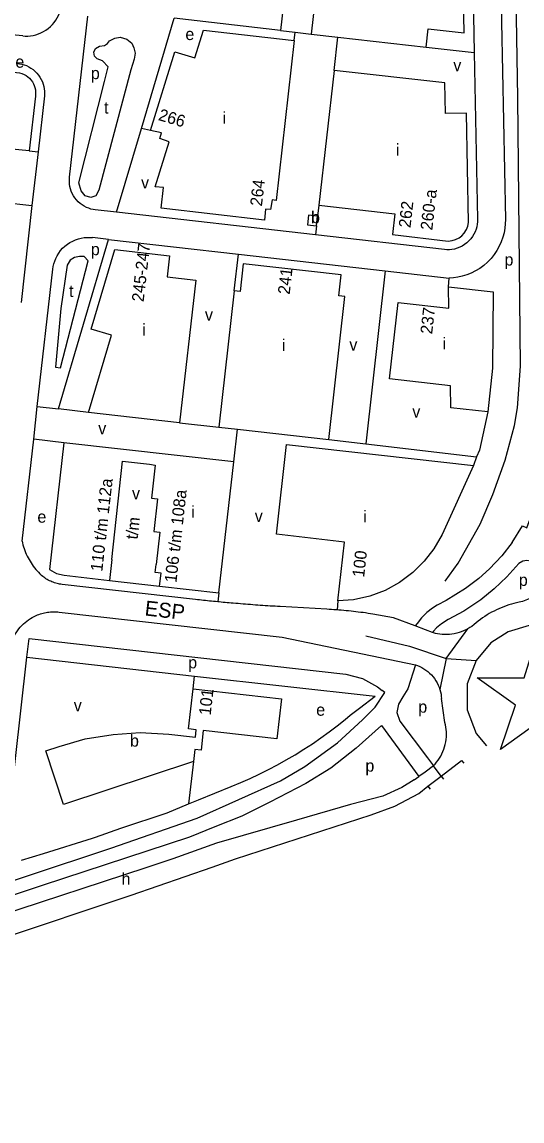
# Model space of a CAD drawing. Extents: x 161394 to 163917, y 388470 to 389774.
# Drawn here: x 162341 to 162508, y 388499 to 388866.6 of the extents above; entities that cross this region are included whole.
import ezdxf

# ---------------------------------------------------------------- set-up
doc = ezdxf.new("R2010")
doc.units = 0
for name, color, linetype in [('BLT_Basislijn', 7, 'Continuous'), ('BLT_Bebouwing', 7, 'Continuous'), ('BLT_Centroide', 7, 'Continuous'), ('BLT_Huisnummer', 7, 'Continuous'), ('BLT_Huisnummer_reeks', 7, 'Continuous'), ('BLT_Straatnaam', 7, 'Continuous'), ('BLT_Vlakafsluiter', 7, 'Continuous')]:
    doc.layers.add(name, color=color, linetype=linetype)

msp = doc.modelspace()

# ---------------------------------------------------------------- linework, layer by layer
at = {"layer": 'BLT_Basislijn'}
for p, q in [((162506.63, 388841.21), (162505.13, 388944.2)), ((162491.22, 388898.12), (162492.06, 388856.45)), ((162356.83, 388814.71), (162362.93, 388868.63)), ((162427.37, 388863.83), (162432.26, 388863.19)), ((162431.95, 388860.46), (162432.26, 388863.19)), ((162432.26, 388863.19), (162437.61, 388862.58)), ((162365.5, 388857.74), (162366.81, 388858.52)), ((162366.81, 388858.52), (162368.51, 388858.75)), ((162368.51, 388858.75), (162369.48, 388859.46)), ((162369.48, 388859.46), (162370.25, 388860.33)), ((162370.25, 388860.33), (162372.01, 388861.18)), ((162372.01, 388861.18), (162373.71, 388861.54)), ((162373.71, 388861.54), (162376.04, 388860.94)), ((162376.04, 388860.94), (162377.68, 388859.56)), ((162377.68, 388859.56), (162378.32, 388858.02)), ((162445.29, 388850.44), (162446.55, 388861.57)), ((162476.03, 388858.25), (162492.06, 388856.45)), ((162365.01, 388856.53), (162365.5, 388857.74)), ((162365.22, 388855.15), (162365.01, 388856.53)), ((162366.1, 388854.3), (162365.22, 388855.15)), ((162378.32, 388858.02), (162378.75, 388856.22)), ((162378.75, 388856.22), (162378.42, 388854.16)), ((162492.06, 388856.45), (162493.18, 388800.64)), ((162367.88, 388853.65), (162366.1, 388854.3)), ((162369.8, 388851.68), (162367.88, 388853.65)), ((162368.53, 388846.69), (162369.8, 388851.68)), ((162378.42, 388854.16), (162377.35, 388850.68)), ((162377.35, 388850.68), (162366.67, 388810.36)), ((162359.93, 388812.83), (162368.53, 388846.69)), ((162348.44, 388841.91), (162346.32, 388823.16)), ((162383.92, 388830.34), (162380.86, 388831)), ((162343.36, 388823.49), (162346.32, 388823.16)), ((162346.32, 388823.16), (162344.29, 388805.2)), ((162360.73, 388810.11), (162359.93, 388812.83)), ((162366.67, 388810.36), (162365.66, 388808.47)), ((162362.09, 388808.52), (162360.73, 388810.11)), ((162363.93, 388807.98), (162362.09, 388808.52)), ((162365.66, 388808.47), (162363.93, 388807.98)), ((162334.33, 388806.33), (162344.29, 388805.2)), ((162344.29, 388805.2), (162340.62, 388772.81)), ((162372.51, 388802.97), (162365.46, 388803.77)), ((162440.17, 388805.32), (162439.74, 388801.68)), ((162439.04, 388795.4), (162372.51, 388802.97)), ((162439.37, 388798.4), (162439.04, 388795.4)), ((162369.83, 388793.91), (162364.52, 388794.52)), ((162482.16, 388790.5), (162439.04, 388795.4)), ((162411.87, 388776.7), (162413.31, 388788.98)), ((162353.86, 388750.98), (162363.07, 388786.74)), ((162356.06, 388785.34), (162353.92, 388770.75)), ((162357.04, 388786.95), (162356.06, 388785.34)), ((162358.52, 388787.88), (162357.04, 388786.95)), ((162360.21, 388788.15), (162358.52, 388787.88)), ((162361.75, 388788.14), (162360.21, 388788.15)), ((162363.07, 388786.74), (162361.75, 388788.14)), ((162462.34, 388783.42), (162455.81, 388725.56)), ((162483.49, 388778.03), (162483.67, 388781)), ((162353.92, 388770.75), (162352.19, 388751.13)), ((162352.19, 388751.13), (162353.86, 388750.98)), ((162346.05, 388738.07), (162353.11, 388737.24)), ((162363.2, 388736.02), (162353.11, 388737.24)), ((162393.63, 388732.56), (162406.69, 388731.15)), ((162411.71, 388719.46), (162412.95, 388730.43)), ((162354.96, 388725.92), (162344.88, 388727.07)), ((162443.44, 388726.97), (162455.81, 388725.56)), ((162455.81, 388725.56), (162492.89, 388721.19)), ((162492.89, 388721.19), (162491.88, 388718.3)), ((162398.97, 388673.46), (162354.42, 388678.5)), ((162406.74, 388675.66), (162406.4, 388672.68)), ((162442.77, 388670.22), (162427.2, 388671.08)), ((162446.49, 388673), (162446.28, 388669.98)), ((162472.34, 388664.6), (162465.1, 388667.35)), ((162475.81, 388663.28), (162472.34, 388664.6)), ((162478.12, 388662.41), (162475.81, 388663.28)), ((162336.75, 388602.35), (162342.6, 388654.12)), ((162472.44, 388651.57), (162469.91, 388643.61)), ((162398.15, 388643.62), (162398.63, 388647.87)), ((162458.99, 388637.41), (162462.26, 388642.32)), ((162462.26, 388642.32), (162461.36, 388643.04)), ((162482.28, 388632.36), (162481.13, 388640.3)), ((162461.09, 388631.3), (162473.61, 388614.26)), ((162398.29, 388619.33), (162396.64, 388605.08)), ((162476.44, 388620.48), (162478.46, 388617.83)), ((162475.64, 388615.75), (162473.61, 388614.26)), ((162478.46, 388617.83), (162475.64, 388615.75)), ((162472.04, 388613.1), (162473.61, 388614.26)), ((162481.05, 388614.41), (162481.82, 388613.39)), ((162476.62, 388610.98), (162477.39, 388609.97)), ((162382.33, 388583.76), (162305.41, 388558.5)), ((162214.71, 388520.22), (162377.39, 388574.62))]:
    msp.add_line(p, q, dxfattribs=at)
for points in [[(162495.1, 389075.02), (162497.51, 389048.21), (162502.48, 388800.58)], [(162341.2, 388861.95), (162241.66, 388870.97)], [(162341.2, 388861.95), (162342.04, 388861.9), (162342.9, 388861.91), (162343.78, 388861.99), (162344.67, 388862.13), (162345.55, 388862.35), (162346.43, 388862.64), (162347.3, 388862.99), (162348.13, 388863.42), (162348.94, 388863.91), (162349.71, 388864.47), (162350.43, 388865.08), (162351.1, 388865.75), (162351.7, 388866.46), (162352.25, 388867.21), (162352.73, 388867.98), (162353.14, 388868.78), (162353.49, 388869.59), (162353.77, 388870.4), (162353.94, 388871.01)], [(162380.86, 388831), (162391.86, 388867.87)], [(162339.39, 388852.77), (162340.14, 388852.68), (162340.9, 388852.53), (162341.67, 388852.31), (162342.44, 388852.03), (162343.19, 388851.67), (162343.92, 388851.24), (162344.63, 388850.75), (162345.29, 388850.19), (162345.91, 388849.57), (162346.47, 388848.9), (162346.96, 388848.18), (162347.39, 388847.43), (162347.75, 388846.65), (162348.04, 388845.85), (162348.25, 388845.04), (162348.4, 388844.24), (162348.47, 388843.44), (162348.49, 388842.67), (162348.44, 388841.91)], [(162502.45, 388720.06), (162505.5, 388731.68), (162506.52, 388737.54), (162507.51, 388751.47), (162506.63, 388841.21)], [(162372.51, 388802.97), (162380.86, 388831)], [(162365.46, 388803.77), (162364.73, 388803.89), (162363.98, 388804.07), (162363.24, 388804.31), (162362.5, 388804.62), (162361.77, 388804.99), (162361.06, 388805.44), (162360.39, 388805.94), (162359.76, 388806.51), (162359.17, 388807.13), (162358.64, 388807.81), (162358.17, 388808.52), (162357.77, 388809.27), (162357.43, 388810.04), (162357.16, 388810.83), (162356.97, 388811.63), (162356.84, 388812.42), (162356.78, 388813.2), (162356.78, 388813.97), (162356.83, 388814.71)], [(162493.18, 388800.64), (162493.17, 388799.83), (162493.09, 388799.01), (162492.94, 388798.17), (162492.71, 388797.32), (162492.4, 388796.48), (162492, 388795.65), (162491.52, 388794.85), (162490.96, 388794.09), (162490.33, 388793.38), (162489.63, 388792.74), (162488.87, 388792.17), (162488.07, 388791.67), (162487.23, 388791.26), (162486.37, 388790.93), (162485.51, 388790.69), (162484.64, 388790.53), (162483.79, 388790.45), (162482.96, 388790.44), (162482.16, 388790.5)], [(162502.48, 388800.58), (162502.45, 388799.13), (162502.31, 388797.64), (162502.05, 388796.14), (162501.65, 388794.62), (162501.13, 388793.11), (162500.46, 388791.63), (162499.67, 388790.19), (162498.74, 388788.81), (162497.7, 388787.51), (162496.54, 388786.3), (162495.28, 388785.2), (162493.94, 388784.22), (162492.53, 388783.37), (162491.08, 388782.65), (162489.59, 388782.06), (162488.09, 388781.61), (162486.6, 388781.28), (162485.12, 388781.08), (162483.67, 388781)], [(162351.24, 388783.94), (162351.38, 388784.84), (162351.59, 388785.75), (162351.88, 388786.66), (162352.24, 388787.57), (162352.7, 388788.46), (162353.23, 388789.32), (162353.84, 388790.15), (162354.53, 388790.93), (162355.29, 388791.65), (162356.11, 388792.3), (162356.98, 388792.88), (162357.89, 388793.37), (162358.83, 388793.78), (162359.79, 388794.11), (162360.76, 388794.35), (162361.73, 388794.51), (162362.68, 388794.58), (162363.62, 388794.59), (162364.52, 388794.52)], [(162353.11, 388737.24), (162369.83, 388793.91)], [(162369.83, 388793.91), (162413.31, 388788.98)], [(162413.31, 388788.98), (162462.34, 388783.42)], [(162346.05, 388738.07), (162351.24, 388783.94)], [(162462.34, 388783.42), (162483.67, 388781)], [(162504.76, 388692.48), (162508.27, 388698.15), (162509.67, 388697.38), (162515.69, 388713.62), (162516.59, 388719.1), (162516.71, 388731.13), (162517.37, 388777.82)], [(162344.88, 388727.07), (162346.05, 388738.07)], [(162496.59, 388736.18), (162493.83, 388723.46), (162492.89, 388721.19)], [(162340.96, 388693.01), (162344.88, 388727.07)], [(162482.39, 388679.55), (162486.74, 388685.56), (162494.04, 388698.67), (162498.29, 388708.58), (162502.45, 388720.06)], [(162340.96, 388693.01), (162341.11, 388692.37), (162341.28, 388691.73), (162341.46, 388691.1), (162341.67, 388690.47), (162341.9, 388689.85), (162342.14, 388689.23), (162342.4, 388688.62), (162342.68, 388688.01), (162342.99, 388687.42), (162343.3, 388686.83), (162343.64, 388686.25), (162343.99, 388685.69), (162344.36, 388685.13), (162344.74, 388684.59), (162345.14, 388684.06), (162345.55, 388683.54), (162345.98, 388683.04), (162346.42, 388682.55), (162346.87, 388682.07)], [(162504.76, 388692.48), (162501.27, 388688.08), (162497.22, 388683.77), (162493.59, 388680.46), (162489.12, 388677.13), (162482.69, 388673.13), (162479.71, 388671.62), (162478.09, 388670.6), (162476.19, 388669.06), (162474.48, 388667.31), (162472.96, 388665.39), (162472.34, 388664.6)], [(162510.87, 388686.25), (162509.61, 388686.46), (162508.35, 388686.31), (162507.01, 388685.54), (162503.02, 388681.07), (162498.79, 388677.01), (162494.25, 388673.31), (162488.61, 388669.52), (162483.41, 388666.77), (162481.14, 388665.29), (162479.49, 388663.98), (162478.46, 388662.9), (162478.12, 388662.41)], [(162354.42, 388678.5), (162353.98, 388678.56), (162353.54, 388678.63), (162353.11, 388678.72), (162352.67, 388678.82), (162352.24, 388678.94), (162351.81, 388679.07), (162351.38, 388679.22), (162350.96, 388679.39), (162350.55, 388679.57), (162350.14, 388679.76), (162349.74, 388679.97), (162349.35, 388680.19), (162348.96, 388680.42), (162348.59, 388680.67), (162348.22, 388680.93), (162347.87, 388681.2), (162347.52, 388681.48), (162347.19, 388681.77), (162346.87, 388682.07)], [(162370.18, 388679.81), (162386.95, 388677.95)], [(162515.67, 388679.32), (162515.41, 388678.8), (162515.13, 388678.28), (162514.83, 388677.78), (162514.49, 388677.29), (162514.13, 388676.81), (162513.74, 388676.35), (162513.33, 388675.9), (162512.89, 388675.48), (162512.43, 388675.08), (162511.96, 388674.7), (162511.46, 388674.34), (162510.95, 388674.02), (162510.42, 388673.71), (162509.88, 388673.44), (162509.33, 388673.2), (162508.78, 388672.99), (162508.21, 388672.8), (162507.65, 388672.64), (162507.09, 388672.52)], [(162406.4, 388672.68), (162405.58, 388672.76), (162404.92, 388672.83), (162404.26, 388672.89), (162403.6, 388672.96), (162402.93, 388673.03), (162402.27, 388673.1), (162401.61, 388673.17), (162400.95, 388673.24), (162400.29, 388673.32), (162399.63, 388673.39), (162398.97, 388673.46)], [(162411.53, 388672.22), (162410.87, 388672.28), (162410.21, 388672.33), (162409.55, 388672.39), (162408.89, 388672.45), (162408.22, 388672.51), (162407.56, 388672.57), (162406.9, 388672.64), (162406.4, 388672.68)], [(162427.2, 388671.08), (162426.37, 388671.13), (162425.55, 388671.18), (162424.72, 388671.23), (162423.9, 388671.28), (162423.07, 388671.33), (162422.25, 388671.38), (162421.42, 388671.44), (162420.6, 388671.49), (162419.77, 388671.55), (162418.95, 388671.61), (162418.12, 388671.67), (162417.3, 388671.74), (162416.48, 388671.8), (162415.65, 388671.87), (162414.83, 388671.93), (162414, 388672), (162413.18, 388672.08), (162412.36, 388672.15), (162411.53, 388672.22)], [(162507.09, 388672.52), (162506.22, 388672.33), (162505.36, 388672.12), (162504.51, 388671.89), (162503.66, 388671.64), (162502.81, 388671.36), (162501.97, 388671.05), (162501.14, 388670.73), (162500.32, 388670.37), (162499.5, 388670), (162498.7, 388669.6), (162497.91, 388669.18), (162497.13, 388668.75), (162496.37, 388668.29), (162495.61, 388667.8), (162494.88, 388667.3), (162494.16, 388666.78), (162493.45, 388666.24), (162492.76, 388665.69), (162492.09, 388665.12)], [(162336.78, 388656.04), (162336.88, 388656.76), (162337.01, 388657.48), (162337.19, 388658.2), (162337.4, 388658.92), (162337.64, 388659.63), (162337.93, 388660.34), (162338.25, 388661.02), (162338.6, 388661.7), (162339, 388662.36), (162339.42, 388662.99), (162339.88, 388663.61), (162340.36, 388664.2), (162340.88, 388664.76), (162341.41, 388665.29), (162341.98, 388665.79), (162342.56, 388666.26), (162343.16, 388666.7), (162343.77, 388667.1), (162344.4, 388667.47)], [(162344.4, 388667.47), (162344.82, 388667.7), (162345.26, 388667.91), (162345.7, 388668.11), (162346.15, 388668.3), (162346.61, 388668.47), (162347.08, 388668.63), (162347.55, 388668.77), (162348.02, 388668.9), (162348.5, 388669.01), (162348.99, 388669.11), (162349.47, 388669.19), (162349.96, 388669.26), (162350.45, 388669.3), (162350.94, 388669.34), (162351.43, 388669.35), (162351.92, 388669.35), (162352.4, 388669.34), (162352.89, 388669.31), (162353.37, 388669.26)], [(162353.37, 388669.26), (162427.9, 388660.84), (162472.44, 388651.57)], [(162446.28, 388669.98), (162446.04, 388670), (162445.22, 388670.06), (162444.41, 388670.12), (162443.59, 388670.17), (162442.77, 388670.22)], [(162458.21, 388668.59), (162457.4, 388668.71), (162456.59, 388668.83), (162455.78, 388668.95), (162454.97, 388669.06), (162454.16, 388669.16), (162453.35, 388669.27), (162452.54, 388669.36), (162451.73, 388669.46), (162450.92, 388669.55), (162450.11, 388669.64), (162449.29, 388669.72), (162448.48, 388669.79), (162447.67, 388669.87), (162446.85, 388669.94), (162446.28, 388669.98)], [(162465.1, 388667.35), (162458.21, 388668.59)], [(162489.94, 388663.64), (162489.24, 388663.27), (162488.51, 388662.93), (162487.76, 388662.63), (162487, 388662.37), (162486.22, 388662.16), (162485.43, 388661.98), (162484.63, 388661.85), (162483.82, 388661.76), (162483.02, 388661.72), (162482.22, 388661.71), (162481.42, 388661.75), (162480.64, 388661.83), (162479.86, 388661.96), (162479.1, 388662.12), (162478.12, 388662.41)], [(162492.09, 388665.12), (162491.27, 388664.48), (162490.62, 388664.05), (162489.94, 388663.64)], [(162537.38, 388640.89), (162536.34, 388647.86), (162532.8, 388654.99), (162526.62, 388660.91), (162518.66, 388664.3), (162510.47, 388664.71), (162503.37, 388662.7), (162497.64, 388659), (162492.72, 388653.1)], [(162342.6, 388654.12), (162343.32, 388660.43), (162449.21, 388648.46)], [(162455.83, 388661.33), (162470.48, 388657.88), (162482.75, 388653.74)], [(162342.6, 388654.12), (162398.63, 388647.87)], [(162492.72, 388653.1), (162489.77, 388645.23), (162489.77, 388636.55), (162492.72, 388628.67), (162496.19, 388624.51)], [(162472.44, 388651.57), (162473.15, 388651.33), (162473.87, 388651.04), (162474.57, 388650.69), (162475.26, 388650.3), (162475.93, 388649.86), (162476.58, 388649.37), (162477.19, 388648.84), (162477.78, 388648.26), (162478.32, 388647.64), (162478.83, 388646.99), (162479.29, 388646.3), (162479.7, 388645.59), (162480.06, 388644.86), (162480.37, 388644.11), (162480.62, 388643.35)], [(162398.63, 388647.87), (162459.02, 388641.13)], [(162449.21, 388648.46), (162454.76, 388647.08), (162459.75, 388644.25), (162461.36, 388643.04)], [(162469.91, 388643.61), (162468.26, 388640.86), (162466.82, 388638.46), (162466.27, 388635.71), (162467.24, 388632.75), (162476.44, 388620.48)], [(162480.62, 388643.35), (162480.83, 388642.58), (162480.98, 388641.82), (162481.08, 388641.05), (162481.13, 388640.3)], [(162453.76, 388637.13), (162459.02, 388641.13)], [(162399.53, 388600.27), (162427.32, 388612.79), (162435.45, 388617.62), (162446.37, 388625.52), (162454.76, 388633.17), (162458.99, 388637.41)], [(162410.88, 388610.93), (162414.03, 388612.24), (162417.15, 388613.61), (162420.24, 388615.06), (162423.3, 388616.58), (162426.31, 388618.17), (162429.29, 388619.83), (162432.23, 388621.56), (162435.13, 388623.36), (162437.98, 388625.23), (162440.79, 388627.16), (162443.55, 388629.16), (162446.27, 388631.22), (162448.94, 388633.35), (162450.63, 388634.75)], [(162450.63, 388634.75), (162453.76, 388637.13)], [(162461.09, 388631.3), (162452.6, 388623.68), (162444.16, 388617.01), (162435.81, 388611.92), (162423.79, 388605.68), (162414.47, 388601.04), (162405.41, 388597.44), (162396.96, 388593.99), (162347.65, 388577.75), (162243.97, 388543.13), (162205.6, 388529.01), (162173.35, 388516.42), (162151.08, 388508.41), (162127, 388500), (162127.4, 388499.02)], [(162478.46, 388617.83), (162479, 388618.41), (162479.52, 388619.03), (162480.02, 388619.68), (162480.48, 388620.36), (162480.9, 388621.07), (162481.29, 388621.82), (162481.64, 388622.58), (162481.94, 388623.37), (162482.2, 388624.18), (162482.42, 388624.99), (162482.59, 388625.83), (162482.71, 388626.66), (162482.78, 388627.5), (162482.81, 388628.34), (162482.79, 388629.17), (162482.73, 388629.99), (162482.62, 388630.8), (162482.47, 388631.59), (162482.28, 388632.36)], [(162481.05, 388614.41), (162487.79, 388619.63), (162488.64, 388618.67)], [(162472.04, 388613.1), (162467.88, 388610.53), (162461.57, 388607.68), (162450.71, 388604.88), (162432.71, 388599.66)], [(162476.62, 388610.98), (162481.05, 388614.41)], [(162377.39, 388574.62), (162404.48, 388583.9), (162412.32, 388586.7), (162457.69, 388601.46), (162465.58, 388604.3), (162473.53, 388608.59), (162476.62, 388610.98)], [(162396.64, 388605.08), (162399.99, 388606.49), (162410.88, 388610.93)], [(162373.99, 388596.95), (162389.5, 388602.05), (162396.64, 388605.08)], [(162286.6, 388562.38), (162370.69, 388590.23), (162399.53, 388600.27)], [(162432.71, 388599.66), (162405.93, 388591.91), (162391.31, 388586.71), (162382.33, 388583.76)], [(162340.8, 388586.23), (162348.14, 388588.53), (162364.48, 388593.58), (162365.51, 388593.94), (162373.99, 388596.95)]]:
    msp.add_lwpolyline(points, dxfattribs=at)
msp.add_lwpolyline([(162493.07, 388647.3), (162508.75, 388647.3), (162513.5, 388662.26), (162518.32, 388647.3), (162534.11, 388647.35), (162521.27, 388638.16), (162526.33, 388623.16), (162513.58, 388632.48), (162500.91, 388623.26), (162505.83, 388638.13)], close=True, dxfattribs=at)
at = {"layer": 'BLT_Bebouwing'}
for p, q in [((162398.71, 388854.63), (162401.57, 388863.93)), ((162401.57, 388863.93), (162431.95, 388860.46)), ((162431.95, 388860.46), (162425.87, 388806.95)), ((162383.92, 388830.34), (162392.01, 388856.69)), ((162392.01, 388856.69), (162398.71, 388854.63)), ((162445.29, 388850.44), (162440.17, 388805.32)), ((162482.31, 388846.26), (162445.29, 388850.44)), ((162482.49, 388836), (162482.31, 388846.26)), ((162489.49, 388836.13), (162482.49, 388836)), ((162490.18, 388799.6), (162489.49, 388836.13)), ((162387.58, 388829.55), (162383.92, 388830.34)), ((162387, 388827.68), (162387.58, 388829.55)), ((162385.44, 388811.53), (162390.08, 388826.54)), ((162390.08, 388826.54), (162387, 388827.68)), ((162388.28, 388811.24), (162385.44, 388811.53)), ((162387.48, 388804.31), (162388.28, 388811.24)), ((162424.57, 388807.11), (162423.98, 388803.86)), ((162425.87, 388806.95), (162424.57, 388807.11)), ((162421.94, 388800.37), (162387.48, 388804.31)), ((162422.31, 388804.07), (162421.94, 388800.37)), ((162423.98, 388803.86), (162422.31, 388804.07)), ((162440.17, 388805.32), (162465.55, 388802.46)), ((162439.37, 388798.4), (162439.74, 388801.68)), ((162465.55, 388802.46), (162464.76, 388795.5)), ((162364.03, 388763.89), (162371.93, 388790.53)), ((162483.49, 388778.03), (162498.44, 388776.34)), ((162483.62, 388770.93), (162483.49, 388778.03)), ((162498.44, 388776.34), (162498.17, 388750.82)), ((162463.73, 388747.29), (162466.63, 388772.83)), ((162466.63, 388772.83), (162483.62, 388770.93)), ((162370.88, 388761.85), (162364.03, 388763.89)), ((162363.2, 388736.02), (162370.88, 388761.85)), ((162484.13, 388744.9), (162463.73, 388747.29)), ((162484.26, 388737.57), (162484.13, 388744.9)), ((162496.59, 388736.18), (162484.26, 388737.57)), ((162393.63, 388732.56), (162363.2, 388736.02)), ((162374.57, 388719.77), (162383.52, 388718.76)), ((162370.95, 388686.81), (162370.18, 388679.81))]:
    msp.add_line(p, q, dxfattribs=at)
for points in [[(162488.22, 388886.92), (162440.94, 388892.21), (162437.61, 388862.58)], [(162430.25, 388889.19), (162427.37, 388863.83)], [(162476.03, 388858.25), (162476.73, 388864.3), (162488.71, 388862.96), (162488.46, 388874.49), (162486.86, 388874.68), (162487.16, 388877.41), (162488.46, 388877.25), (162488.44, 388886.59), (162488.18, 388886.56), (162488.22, 388886.92)], [(162427.37, 388863.83), (162391.86, 388867.87)], [(162437.61, 388862.58), (162446.55, 388861.57)], [(162446.55, 388861.57), (162476.03, 388858.25)], [(162287.81, 388854.44), (162339.11, 388849.78), (162340.07, 388849.63), (162340.9, 388849.4), (162341.64, 388849.08), (162342.29, 388848.73), (162342.9, 388848.3), (162343.45, 388847.82), (162343.94, 388847.26), (162344.43, 388846.63), (162344.79, 388845.97), (162345.05, 388845.4), (162345.24, 388844.73), (162345.43, 388843.96), (162345.5, 388843.35), (162345.5, 388842.68), (162345.44, 388841.77), (162343.36, 388823.49)], [(162343.36, 388823.49), (162336.4, 388824.26), (162335.6, 388817.32), (162284.26, 388823.09)], [(162439.74, 388801.68), (162436.75, 388802.02), (162436.39, 388798.74), (162439.37, 388798.4)], [(162464.76, 388795.5), (162483.39, 388793.36), (162484.67, 388793.53), (162485.88, 388793.87), (162487, 388794.44), (162487.94, 388795.15), (162488.76, 388796.04), (162489.47, 388797.17), (162489.94, 388798.34), (162490.18, 388799.6)], [(162371.93, 388790.53), (162390.21, 388788.47), (162389.44, 388781.37), (162399.06, 388780.3), (162393.63, 388732.56)], [(162443.44, 388726.97), (162448.88, 388774.85), (162446.81, 388775.09), (162447.61, 388782.05), (162414.92, 388785.77), (162413.86, 388776.48)], [(162411.87, 388776.7), (162406.69, 388731.15)], [(162413.86, 388776.48), (162411.87, 388776.7)], [(162498.17, 388750.82), (162496.59, 388736.18)], [(162406.69, 388731.15), (162412.95, 388730.43)], [(162412.95, 388730.43), (162443.44, 388726.97)], [(162354.96, 388725.92), (162350.14, 388683.53), (162352.52, 388682.21), (162355.1, 388681.56)], [(162411.71, 388719.46), (162354.96, 388725.92)], [(162446.49, 388673), (162448.71, 388692.67), (162425.97, 388695.28), (162429.38, 388725.33), (162491.88, 388718.3)], [(162370.95, 388686.81), (162374.57, 388719.77)], [(162383.52, 388718.76), (162385.48, 388718.41), (162384.26, 388707.34), (162386.2, 388707.13), (162385, 388696.24), (162386.96, 388696.02), (162385.77, 388685.17)], [(162406.74, 388675.66), (162411.71, 388719.46)], [(162491.88, 388718.3), (162481.33, 388695.24), (162478.59, 388690.42), (162475.4, 388686.27), (162471.6, 388682.5), (162467.09, 388679.14), (162462.27, 388676.52), (162457.17, 388674.61), (162451.69, 388673.4), (162446.49, 388673)], [(162386.95, 388677.95), (162387.45, 388682.31), (162385.47, 388682.53), (162385.77, 388685.17)], [(162355.1, 388681.56), (162370.18, 388679.81)], [(162386.95, 388677.95), (162406.74, 388675.66)], [(162398.29, 388619.33), (162354.87, 388604.89), (162348.9, 388622.86), (162353.33, 388624.32), (162362.11, 388626.86), (162371.45, 388628.34), (162380.48, 388628.93), (162390.02, 388628.44), (162398.94, 388627.41), (162399.2, 388629.89), (162396.63, 388630.18), (162398.15, 388643.62)], [(162398.15, 388643.62), (162427.7, 388640.27), (162426.14, 388626.84), (162401.55, 388629.6), (162400.82, 388623.09), (162398.74, 388623.32), (162398.29, 388619.33)]]:
    msp.add_lwpolyline(points, dxfattribs=at)
at = {"layer": 'BLT_Vlakafsluiter'}
for p, q in [((162482.75, 388653.74), (162489.94, 388663.64)), ((162482.75, 388653.74), (162480.62, 388643.35)), ((162482.75, 388653.74), (162492.72, 388653.1)), ((162481.05, 388614.41), (162478.46, 388617.83))]:
    msp.add_line(p, q, dxfattribs=at)

# ---------------------------------------------------------------- texts
at = {"layer": 'BLT_Centroide'}
for s, p in [('e', (162395.56, 388860.59)), ('e', (162338.75, 388851.34)), ('v', (162485.09, 388850.17)), ('p', (162363.96, 388847.51)), ('t', (162368.36, 388836.01)), ('i', (162407.94, 388832.59)), ('i', (162465.91, 388821.91)), ('v', (162380.75, 388810.96)), ('b', (162437.56, 388799.32)), ('p', (162363.96, 388788.63)), ('p', (162502.2, 388785.17)), ('t', (162356.66, 388774.66)), ('v', (162402.1, 388766.73)), ('i', (162381.09, 388761.72)), ('i', (162427.78, 388756.53)), ('v', (162450.36, 388756.72)), ('i', (162481.54, 388757.09)), ('v', (162471.39, 388734.31)), ('v', (162366.44, 388728.73)), ('v', (162377.72, 388706.99)), ('i', (162397.55, 388700.78)), ('e', (162346.11, 388699.15)), ('v', (162418.74, 388699.4)), ('i', (162454.99, 388699.22)), ('p', (162506.99, 388678.02)), ('p', (162396.49, 388650.43)), ('v', (162358.26, 388636.07)), ('e', (162439.28, 388634.58)), ('p', (162473.4, 388635.61)), ('b', (162377.05, 388624.25)), ('p', (162455.72, 388615.89)), ('h', (162374.21, 388578.04))]:
    msp.add_text(s, height=4, dxfattribs=at).set_placement(p)
at = {"layer": 'BLT_Huisnummer'}
for s, rotation, p in [('241', 83.5075, (162430.4, 388775.35)), ('237', 83.5154, (162478.01, 388762.07)), ('100', 83.5125, (162455.28, 388680.73)), ('101', 83.5478, (162403.99, 388634.56))]:
    msp.add_text(s, height=4, rotation=rotation, dxfattribs=at).set_placement(p)
at = {"layer": 'BLT_Huisnummer_reeks'}
for s, rotation, p in [('266', 343.5134, (162386.25, 388833.88)), ('264', 83.5117, (162421.13, 388804.85)), ('260-a', 83.5134, (162478.06, 388796.82)), ('262', 83.5125, (162470.77, 388797.62)), ('245-247', 83.5121, (162381.59, 388772.86)), ('110 t/m 112a', 83.5487, (162367.78, 388682.71)), ('106 t/m 108a', 83.6111, (162392.55, 388678.95)), ('t/m', 83.6111, (162379.54, 388693.42))]:
    msp.add_text(s, height=4, rotation=rotation, dxfattribs=at).set_placement(p)
at = {"layer": 'BLT_Straatnaam'}
msp.add_text('ESP', height=5, rotation=353.5497, dxfattribs=at).set_placement((162381.8, 388668.15))

doc.saveas('drawing.dxf')
